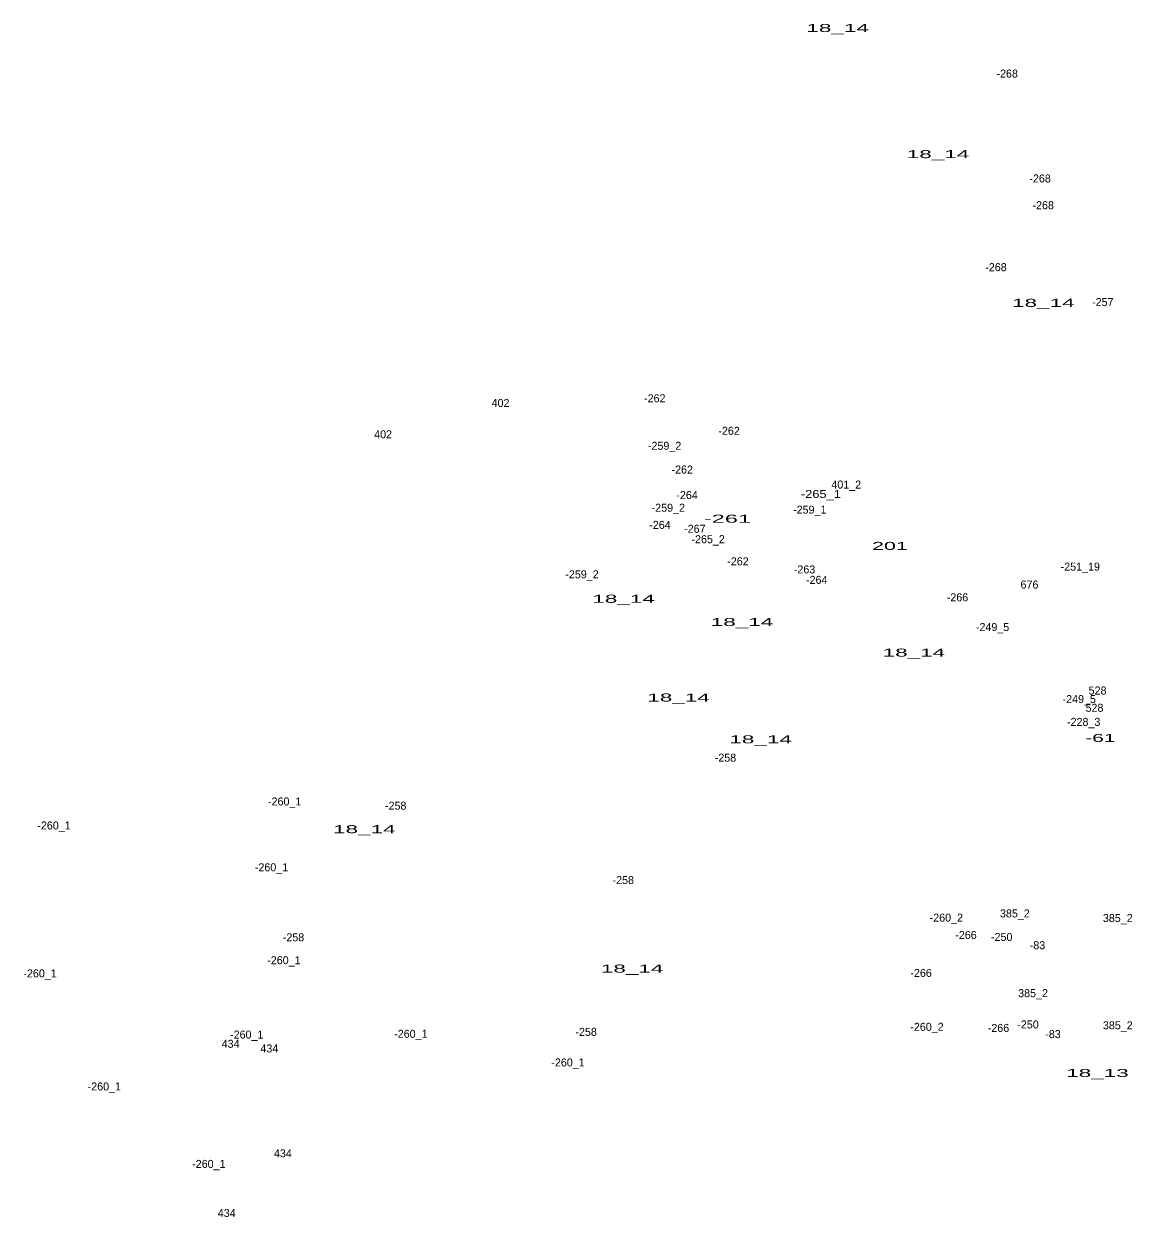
# Model space of a CAD drawing. Extents: x -661742 to -657295, y -1002932 to -996888.
# Drawn here: x -661742 to -661188, y -1002120 to -1001524 of the extents above; entities that cross this region are included whole.
import ezdxf
from ezdxf.enums import TextEntityAlignment as Align

# ---------------------------------------------------------------- set-up
doc = ezdxf.new("R2010")
doc.units = 0
doc.header["$LTSCALE"] = 1.6
doc.layers.add('24', color=7, linetype='Continuous')

msp = doc.modelspace()

# ---------------------------------------------------------------- texts
at = {"layer": '24'}
for s, width, p in [('18_14', 2.1, (-661335.271, -1001527.67)), ('18_14', 2.1, (-661285.111, -1001590.7)), ('18_14', 2.1, (-661232.501, -1001664.99)), ('-265_1', 1.2, (-661343.65, -1001760.5)), ('-261', 2.2, (-661390.335, -1001772.85)), ('201', 2, (-661309.144, -1001786.44)), ('18_14', 2.1, (-661442.231, -1001812.85)), ('18_14', 2.1, (-661383.051, -1001824.46)), ('18_14', 2.1, (-661297.171, -1001839.74)), ('18_14', 2.1, (-661414.761, -1001862.18)), ('18_14', 2.1, (-661373.761, -1001883.08)), ('-61', 1.95, (-661203.995, -1001882.38)), ('18_14', 2.1, (-661571.801, -1001927.96)), ('18_14', 2.1, (-661437.971, -1001997.61)), ('18_13', 2.1, (-661205.445, -1002049.76))]:
    msp.add_text(s, height=4, dxfattribs=dict(at, width=width)).set_placement(p, align=Align.CENTER)
for s, p in [('-268', (-661250.54, -1001550.43)), ('-268', (-661234.11, -1001602.86)), ('-268', (-661232.56, -1001616.21)), ('-268', (-661256.15, -1001647.17)), ('-257', (-661202.781, -1001664.62)), ('402', (-661503.715, -1001715.02)), ('-262', (-661426.65, -1001712.68)), ('402', (-661562.405, -1001730.69)), ('-262', (-661389.52, -1001728.93)), ('-259_2', (-661421.738, -1001736.4)), ('-262', (-661412.92, -1001748.28)), ('401_2', (-661330.967, -1001755.79)), ('-264', (-661410.505, -1001761.03)), ('-259_2', (-661419.888, -1001767.36)), ('-259_1', (-661349.202, -1001768.33)), ('-264', (-661424.035, -1001775.93)), ('-267', (-661406.635, -1001777.88)), ('-265_2', (-661399.988, -1001783.09)), ('-262', (-661385.07, -1001794.13)), ('-263', (-661351.81, -1001798.18)), ('-251_19', (-661214.025, -1001796.79)), ('-259_2', (-661463.018, -1001800.64)), ('-264', (-661345.715, -1001803.4)), ('676', (-661239.423, -1001805.76)), ('-266', (-661275.395, -1001812.13)), ('-249_5', (-661257.852, -1001826.98)), ('528', (-661205.387, -1001858.68)), ('-249_5', (-661214.532, -1001862.96)), ('528', (-661206.937, -1001867.31)), ('-228_3', (-661212.332, -1001874.35)), ('-258', (-661391.325, -1001892.24)), ('-260_1', (-661611.586, -1001914.11)), ('-258', (-661556.105, -1001916.23)), ('-260_1', (-661726.846, -1001926.11)), ('-260_1', (-661618.156, -1001947)), ('-258', (-661442.385, -1001953.38)), ('-260_2', (-661280.962, -1001972.16)), ('385_2', (-661246.725, -1001970.06)), ('385_2', (-661195.285, -1001972.38)), ('-258', (-661607.165, -1001982.01)), ('-266', (-661271.135, -1001980.83)), ('-250', (-661253.299, -1001981.81)), ('-83', (-661235.435, -1001985.94)), ('-260_1', (-661611.966, -1001993.44)), ('-260_1', (-661733.816, -1002000.01)), ('-266', (-661293.575, -1001999.79)), ('385_2', (-661237.635, -1002009.89)), ('-250', (-661240.149, -1002025.53)), ('385_2', (-661195.285, -1002025.95)), ('-260_1', (-661630.536, -1002030.58)), ('-260_1', (-661548.536, -1002030.2)), ('-258', (-661460.955, -1002029.22)), ('-260_2', (-661290.632, -1002026.71)), ('-266', (-661254.895, -1002027.27)), ('-83', (-661227.685, -1002030.35)), ('434', (-661638.596, -1002035.19)), ('434', (-661619.256, -1002037.51)), ('-260_1', (-661470.016, -1002044.51)), ('-260_1', (-661701.706, -1002056.51)), ('434', (-661612.486, -1002089.94)), ('-260_1', (-661649.486, -1002095.2)), ('434', (-661640.536, -1002119.74))]:
    msp.add_text(s, height=4, dxfattribs=at).set_placement(p, align=Align.CENTER)

doc.saveas('drawing.dxf')
